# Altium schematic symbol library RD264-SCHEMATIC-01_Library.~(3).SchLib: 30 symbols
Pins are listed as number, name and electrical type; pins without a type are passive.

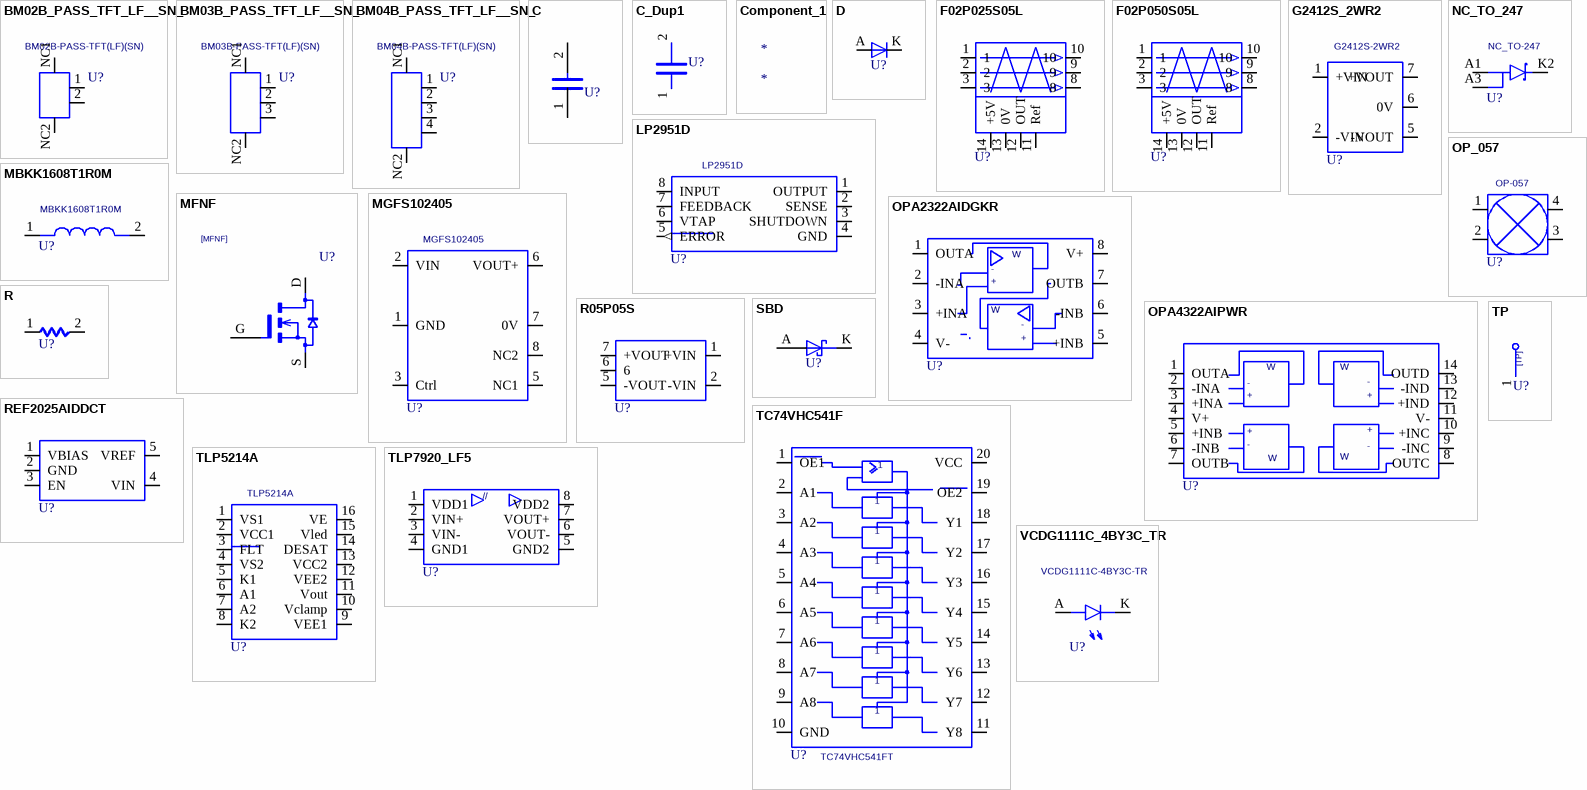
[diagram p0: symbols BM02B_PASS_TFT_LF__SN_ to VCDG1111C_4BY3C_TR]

## BM02B_PASS_TFT_LF__SN_
designator U?, comment BM02B-PASS-TFT(LF)(SN)
PA Connector; MAKER: JST; NOTE: 2pin; TIME: 14:31:25; UPDATEUSER: t5459927; UPDATETIME: 15:09:13; SAVECOUNT: 2; SAVEAREA0: -5711,-13828,12927,-163; OriginalSymbolOrigin: (0,0); Altium-Right: 20; Altium-Bottom: 30
pins: 1, 2, NC1 P1, NC2 P2

## BM03B_PASS_TFT_LF__SN_
designator U?, comment BM03B-PASS-TFT(LF)(SN)
PA Connector; MAKER: JST; NOTE: 3pin; TIME: 14:31:24; UPDATEUSER: t5459927; UPDATETIME: 15:09:29; SAVECOUNT: 2; SAVEAREA0: -7641,-13019,14724,3377; OriginalSymbolOrigin: (0,0); Altium-Right: 20; Altium-Bottom: 40
pins: 1, 2, 3, NC1 P1, NC2 P2

## BM04B_PASS_TFT_LF__SN_
designator U?, comment BM04B-PASS-TFT(LF)(SN)
PA Connector; MAKER: JST; NOTE: 4pin; TIME: 14:31:24; UPDATEUSER: t5459927; UPDATETIME: 15:09:49; SAVECOUNT: 2; SAVEAREA0: -9526,-15610,16566,3519; OriginalSymbolOrigin: (0,0); Altium-Right: 20; Altium-Bottom: 50
pins: 1, 2, 3, 4, NC1 P1, NC2 P2

## C
designator U?  (value not drawn)
OriginalSymbolOrigin: (2540,7620); Altium-Right: 20; Altium-Bottom: 10
pins: 1, 2

## C_Dup1
designator U?, comment C  (value not drawn)
ORIGINALSYMBOLORIGIN: (0,4826); TIME: 14:31:23; UPDATEUSER: t5459927; SAVECOUNT: 1; Altium-Right: 20; Altium-Bottom: 40
pins: 1, 2

## Component_1
designator *

## D
designator U?  (value not drawn)
UPDATEUSER: t5459927; UPDATETIME: 14:31:23; SAVECOUNT: 1; SAVEAREA0: -225,-91,12804,7836; ORIGINALSYMBOLORIGIN: (0,0); Altium-Right: 10; Altium-Bottom: 20
pins: A, K C

## F02P025S05L
designator U?  (value not drawn)
Currnt Transducer; MAKER: Tamura; NOTE: 25At; TIME: 14:31:25; UPDATEUSER: t5459927; UPDATETIME: 08:52:16; SAVECOUNT: 3; SAVEAREA0: -26887,-18217,41699,10476; OriginalSymbolOrigin: (0,0); Altium-Right: 60
pins: 1, 2, 3, 8, 9, 10, 11 Ref, 12 OUT, 13 0V, 14 +5V

## F02P050S05L
designator U?  (value not drawn)
Currnt Transducer; MAKER: Tamura; NOTE: 50At; TIME: 14:31:25; UPDATEUSER: t5459927; UPDATETIME: 14:13:05; SAVECOUNT: 3; SAVEAREA0: -15517,-13418,30208,5711; OriginalSymbolOrigin: (0,0); Altium-Right: 60
pins: 1, 2, 3, 8, 9, 10, 11 Ref, 12 OUT, 13 0V, 14 +5V

## G2412S_2WR2
designator U?, comment G2412S-2WR2
DCDC Converter; MAKER: MORNSUN; NOTE: 24Vin ｱ12Vout; TIME: 14:31:25; UPDATEUSER: t5459927; UPDATETIME: 15:22:21; SAVECOUNT: 2; SAVEAREA0: -5083,-7378,17282,9018; OriginalSymbolOrigin: (0,0); Altium-Right: 50; Altium-Bottom: 60
pins: 1 +VIN, 2 -VIN, 5 -VOUT, 6 0V, 7 +VOUT

## LP2951D
designator U?
IC Regurator; MAKER: Txsas Instruments; TIME: 14:31:24; UPDATEUSER: t5459927; UPDATETIME: 14:27:00; SAVECOUNT: 3; SAVEAREA0: -6711,-14463,34014,2574; OriginalSymbolOrigin: (0,0); Altium-Right: 110; Altium-Bottom: 50
pins: 1 OUTPUT, 2 SENSE, 3 SHUTDOWN, 4 GND, 5 ERROR (out), 6 VTAP, 7 FEEDBACK, 8 INPUT

## MBKK1608T1R0M
designator U?
Inductor; MAKER: Taiyo Yuden; TIME: 14:31:24; UPDATEUSER: t5459927; SAVECOUNT: 1; OriginalSymbolOrigin: (0,0); Altium-Right: 60; Altium-Bottom: 20
pins: 1, 2

## MFNF
designator U?  (value not drawn)
SAVEAREA0: -7027,-292,21786,15988; ORIGINALSYMBOLORIGIN: (0,0); SAVECOUNT: 1; TIME: 14:31:23; UPDATEUSER: t5459927; Altium-Right: 40
pins: D, G, S

## MGFS102405
designator U?
DCDC Converter; MAKER: COSEL; NOTE: 24Vin 5VOut 2A; TIME: 14:31:24; UPDATEUSER: t5459927; UPDATETIME: 15:28:14; SAVECOUNT: 2; SAVEAREA0: -8909,-32686,28368,-5356; OriginalSymbolOrigin: (0,0); Altium-Right: 80; Altium-Bottom: 100
pins: 1 GND, 2 VIN, 3 Ctrl, 5 NC1, 6 VOUT+, 7 0V, 8 NC2

## NC_TO_247
designator U?, comment NC_TO-247
Schottky Barrier Diode; MAKER: NC; TIME: 14:31:25; UPDATEUSER: t5459927; UPDATETIME: 10:54:16; SAVECOUNT: 2; OriginalSymbolOrigin: (0,0); Altium-Right: 30
pins: A1, A3, K2

## OP_057
designator U?, comment OP-057
Terminal Block; MAKER: Osada; NOTE: 85A M5; TIME: 14:31:25; UPDATEUSER: t5459927; UPDATETIME: 15:31:03; SAVECOUNT: 2; SAVEAREA0: -3160,-10780,12927,1014; OriginalSymbolOrigin: (0,0); Altium-Right: 40
pins: 1, 2, 3, 4

## OPA2322AIDGKR
designator U?  (value not drawn)
IC OPAMP; MAKER: Texas Instruments; NOTE: Dual; TIME: 14:31:24; UPDATEUSER: t5459927; UPDATETIME: 14:36:00; SAVECOUNT: 3; SAVEAREA0: -54405,-42613,83055,14894; OriginalSymbolOrigin: (0,0); Altium-Right: 110; Altium-Bottom: 80
pins: 1 OUTA, 2 -INA, 3 +INA, 4 V-, 5 +INB, 6 -INB, 7 OUTB, 8 V+

## OPA4322AIPWR
designator U?  (value not drawn)
IC OPAMP; MAKER: Texas Instruments; NOTE: Quad; TIME: 14:31:23; UPDATEUSER: t5459927; UPDATETIME: 14:10:26; SAVECOUNT: 3; SAVEAREA0: -4407,-29582,46539,7769; OriginalSymbolOrigin: (0,0); Altium-Right: 170; Altium-Bottom: 90
pins: 1 OUTA, 2 -INA, 3 +INA, 4 V+, 5 +INB, 6 -INB, 7 OUTB, 8 OUTC, 9 -INC, 10 +INC, 11 V-, 12 +IND, 13 -IND, 14 OUTD

## R
designator U?  (value not drawn)
ORIGINALSYMBOLORIGIN: (0,0); TIME: 14:31:23; UPDATEUSER: t5459927; SAVECOUNT: 1; Altium-Right: 20
pins: 1, 2

## R05P05S
designator U?  (value not drawn)
DCDC Converter; MAKER: RECOM; NOTE: 5V in 5V out; TIME: 14:31:25; UPDATEUSER: t5459927; UPDATETIME: 15:35:32; SAVECOUNT: 4; SAVEAREA0: -11227,-12811,26358,2912; OriginalSymbolOrigin: (0,0); Altium-Right: 60; Altium-Bottom: 40
pins: 1 +VIN, 2 -VIN, 5 -VOUT, 6, 7 +VOUT

## REF2025AIDDCT
designator U?  (value not drawn)
2Voltage References; MAKER: Texas Instruments; TIME: 14:31:24; UPDATEUSER: t5459927; UPDATETIME: 14:11:39; SAVECOUNT: 3; SAVEAREA0: -3467,-13658,20665,4033; OriginalSymbolOrigin: (0,0); Altium-Right: 70; Altium-Bottom: 40
pins: 1 VBIAS, 2 GND, 3 EN, 4 VIN, 5 VREF

## SBD
designator U?  (value not drawn)
SAVEAREA0: -4630,-153,17114,13055; TIME: 14:49:55; UPDATEUSER: fukuda-y; UPDATETIME: 08:16:22; SAVECOUNT: 9; OriginalSymbolOrigin: (5080,5080); Altium-Right: 20
pins: A, K C

## TC74VHC541F
designator U?, comment TC74VHC541FT
TIME: 14:31:23; UPDATEUSER: t5459927; UPDATETIME: 11:00:49; SAVECOUNT: 3; SAVEAREA0: -14417,-48846,43646,-24554; OriginalSymbolOrigin: (0,0); Altium-Right: 120; Altium-Bottom: 200
pins: 1 OE1, 2 A1, 3 A2, 4 A3, 5 A4, 6 A5, 7 A6, 8 A7, 9 A8, 10 GND, 11 Y8, 12 Y7, 13 Y6, 14 Y5, 15 Y4, 16 Y3, 17 Y2, 18 Y1, 19 OE2, 20 VCC

## TLP5214A
designator U?
Gate Driver; MAKER: TOSHIBA; TIME: 14:31:24; UPDATEUSER: t5459927; UPDATETIME: 14:29:17; SAVECOUNT: 3; SAVEAREA0: -11000,-19257,28193,-2860; OriginalSymbolOrigin: (0,0); Altium-Right: 70; Altium-Bottom: 90
pins: 1 VS1, 2 VCC1, 3 FLT, 4 VS2, 5 K1, 6 A1, 7 A2, 8 K2, 9 VEE1, 10 Vclamp, 11 Vout, 12 VEE2, 13 VCC2, 14 DESAT, 15 Vled, 16 VE

## TLP7920_LF5
designator U?, comment TLP7920(LF5,TP5)  (value not drawn)
Isolation Amplifier; MAKER: TOSHIBA; TIME: 14:31:23; UPDATEUSER: t5459927; UPDATETIME: 14:29:27; SAVECOUNT: 3; SAVEAREA0: -27477,-19134,50054,13301; OriginalSymbolOrigin: (0,0); Altium-Right: 90; Altium-Bottom: 50
pins: 1 VDD1, 2 VIN+, 3 VIN-, 4 GND1, 5 GND2, 6 VOUT-, 7 VOUT+, 8 VDD2

## TP
designator U?  (value not drawn)
TIME: 16:12:21; UPDATEUSER: fukuda-y; UPDATETIME: 16:18:11; SAVECOUNT: 2; SAVEAREA0: -242,-92,12810,7836; OriginalSymbolOrigin: (0,7620); Altium-Right: 20; Altium-Bottom: 30
pins: 1

## VCDG1111C_4BY3C_TR
designator U?, comment VCDG1111C-4BY3C-TR
LED; MAKER: STANLEY; NOTE: Green; TIME: 14:31:24; UPDATEUSER: t5459927; SAVECOUNT: 1; OriginalSymbolOrigin: (0,-2540); Altium-Right: 30
pins: A, K

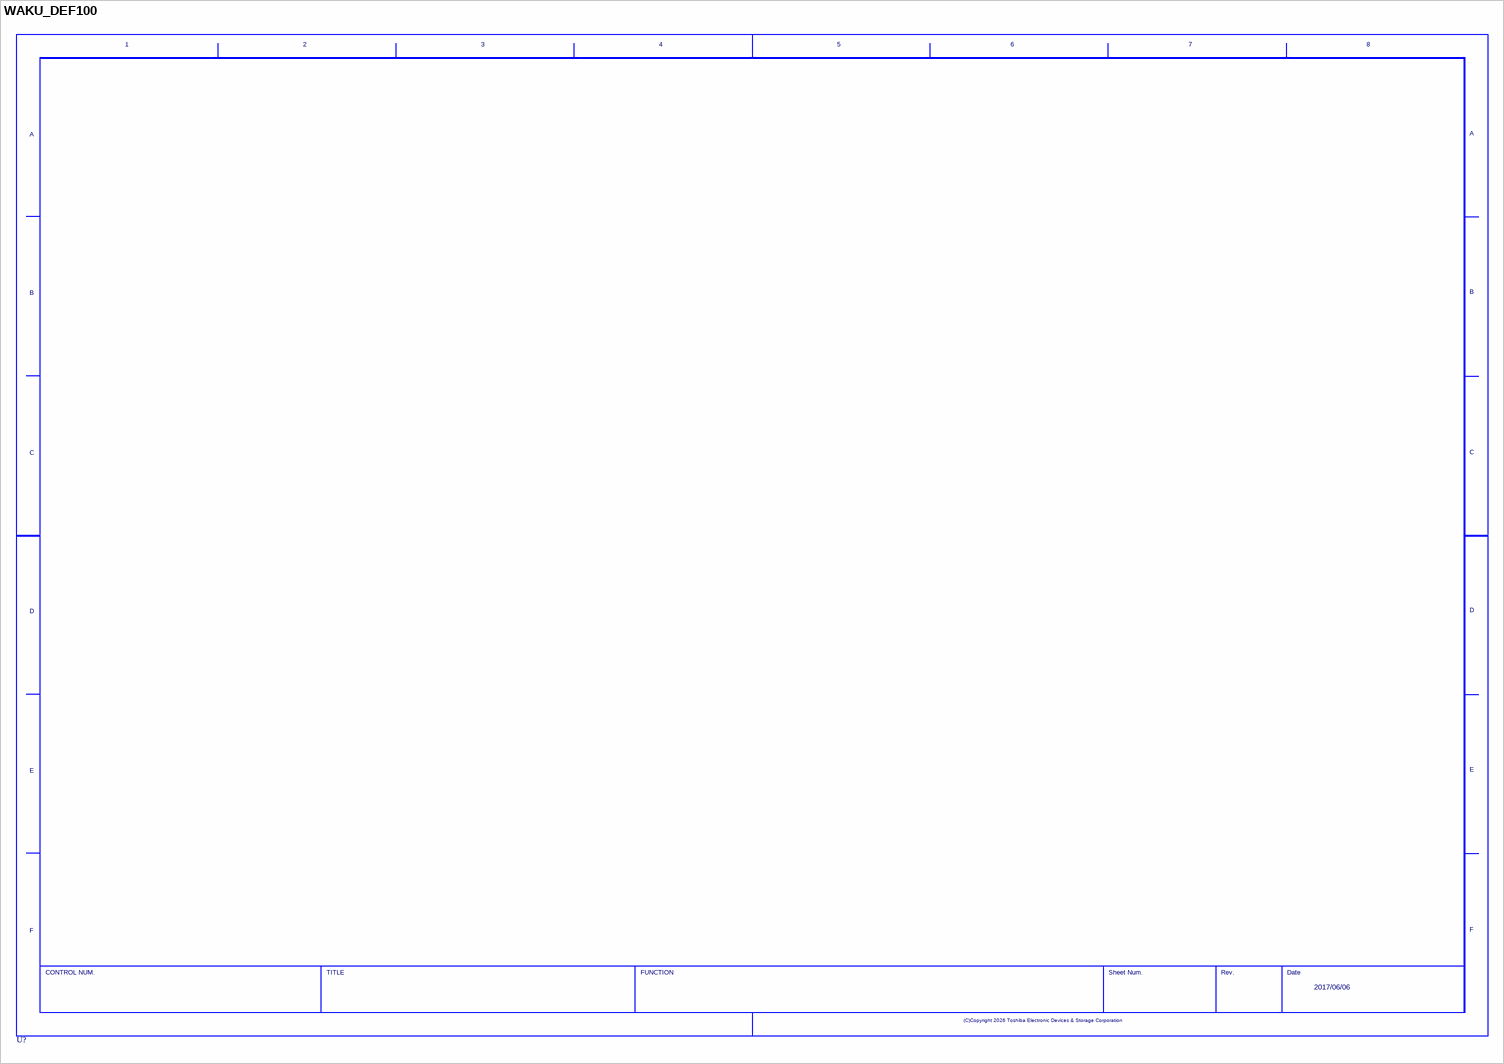
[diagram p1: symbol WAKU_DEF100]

## WAKU_DEF100
designator U?  DATE: 2017/06/06  (hidden comment: WAKU_DEF100)
PLOTTIME: HH:MM; SAVEAREA0: 204655,-40163,430411,63902; TIME: 14:30:25; UPDATEUSER: t5459927; UPDATETIME: 16:20:03; SAVECOUNT: 7; OriginalSymbolOrigin: (10160,284480); Altium-Right: 1570; Altium-Bottom: 1070

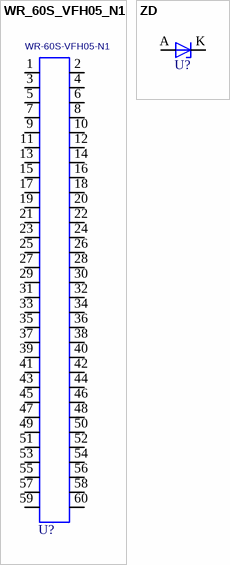
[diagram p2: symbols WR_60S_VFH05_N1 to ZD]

## WR_60S_VFH05_N1
designator U?, comment WR-60S-VFH05-N1
WR Series; MAKER: JAE; NOTE: 60pin; TIME: 14:31:24; UPDATEUSER: t5459927; UPDATETIME: 15:35:07; SAVECOUNT: 2; SAVEAREA0: -56595,-80318,58967,4405; OriginalSymbolOrigin: (0,0); Altium-Right: 20; Altium-Bottom: 310
pins: 1, 2, 3, 4, 5, 6, 7, 8, 9, 10, 11, 12, 13, 14, 15, 16, 17, 18, 19, 20, 21, 22, 23, 24, 25, 26, 27, 28, 29, 30, 31, 32, 33, 34, 35, 36, 37, 38, 39, 40, 41, 42, 43, 44, 45, 46, 47, 48, 49, 50, 51, 52, 53, 54, 55, 56, 57, 58, 59, 60

## ZD
designator U?  (value not drawn)
UPDATEUSER: t5459927; UPDATETIME: 14:31:23; SAVECOUNT: 1; SAVEAREA0: -4630,-153,17114,13055; ORIGINALSYMBOLORIGIN: (0,0); Altium-Right: 10; Altium-Bottom: 20
pins: A, K C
